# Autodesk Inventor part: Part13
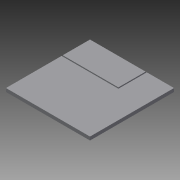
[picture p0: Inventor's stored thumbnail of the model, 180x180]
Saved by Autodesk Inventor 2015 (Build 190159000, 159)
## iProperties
Created: 2015-04
Part Number: Part13
Material: Generic
Document SubType Name: Modeling
Designer: TREINA5
Density: 1 g/cm^3
Appearance: Default
Mass: 129645 g
Surface Area: 48519 cm^2
Volume: 129645 cm^3
Author: TREINA5
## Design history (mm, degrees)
sketch "Sketch1"
  geometry: L1 (8500, 2479.966)-(8500, 2979.966); L2 (8480, 2499.966)-(8480, 2979.966); L3 (8980, 2979.966)-(8980, 1499.966); L4 (7500, 2979.966)-(8480, 2979.966); L5 (7500, 2499.966)-(8480, 2499.966); L6 (7500, 2499.966)-(7500, 2979.966); L7 (7500, 2479.966)-(8500, 2479.966); L8 (7500, 1500)-(8980, 1500); L9 (7500, 1499.966)-(8980, 1499.966); L10 (7500, 1499.966)-(7500, 2479.966); L11 (8500, 2979.966)-(8980, 2979.966); A1 r 1510 centre (5990, 2989.966) between (7499.966, 2999.966) and (7499.966, 3000); 1 further point
  constraints: 22 end point, 2 point on circle, 2 point on line, 1 centre point
extrude "Extrusion1" new body sketch "Sketch1" distance "d0" = 60; taper "d1" = 0 deg
extrude "Extrusion2" new body sketch "Sketch1" distance "d2" = 60; taper "d3" = 0 deg
body "Solid1"
body "Solid2"
